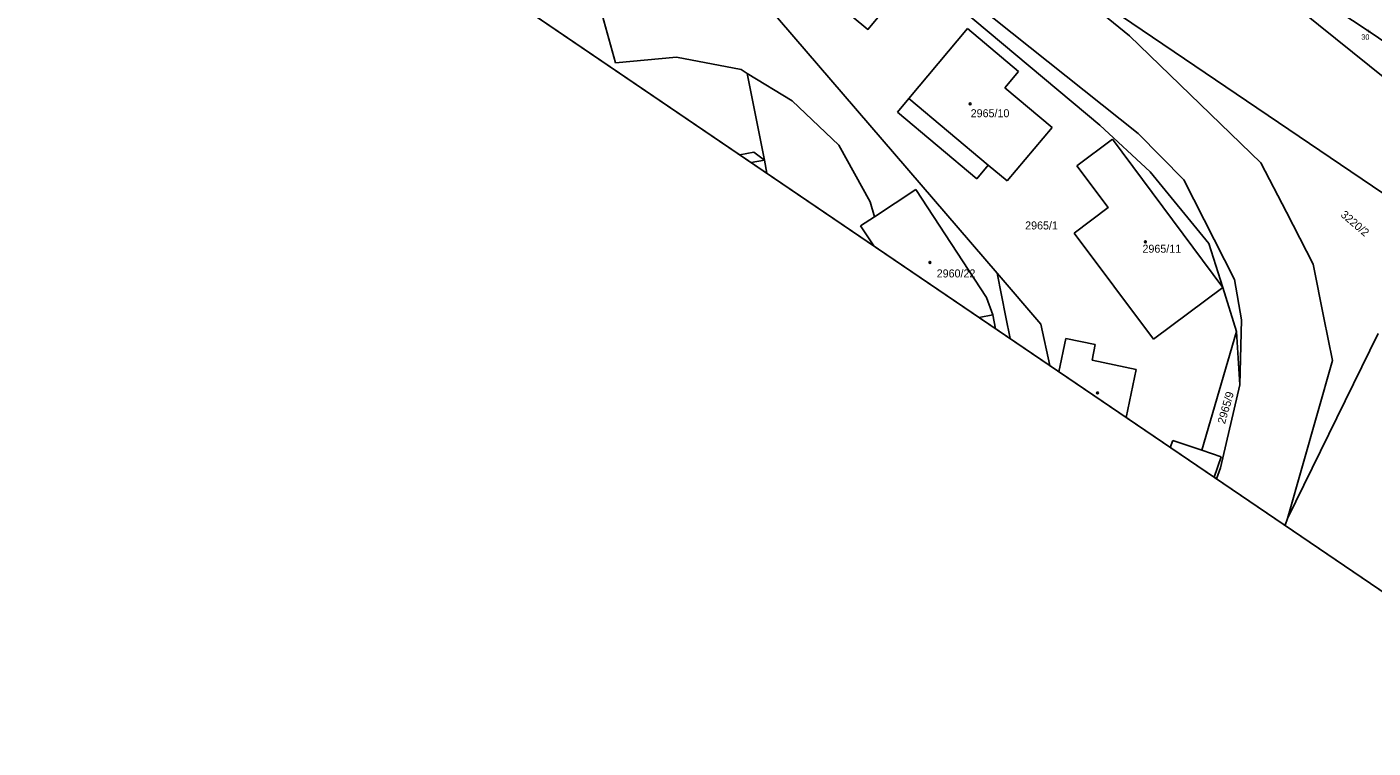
# Model space of a CAD drawing. Extents: x -621058 to -620110, y -1122807 to -1122030.
# Drawn here: x -620573.6 to -620321.3, y -1122806.7 to -1122671.6 of the extents above; entities that cross this region are included whole.
import ezdxf

# ---------------------------------------------------------------- set-up
doc = ezdxf.new("R2010")
doc.units = 0
for name, color, linetype in [('060601_EOV', 7, 'Continuous'), ('BODY', 7, 'Continuous'), ('BODY POPIS', 7, 'Continuous'), ('RÁMY', 7, 'Continuous'), ('Vrstva 53', 7, 'Continuous'), ('Vrstva 55', 7, 'Continuous'), ('Vrstva 56', 7, 'Continuous'), ('Vrstva 57', 7, 'Continuous')]:
    doc.layers.add(name, color=color, linetype=linetype)

msp = doc.modelspace()

# ---------------------------------------------------------------- linework, layer by layer
at = {"layer": '060601_EOV'}
msp.add_lwpolyline([(-620235.16, -1122712.24), (-620240.17, -1122718.34), (-620243.03, -1122716), (-620248.32, -1122722.77), (-620259.89, -1122713.57), (-620277.71, -1122700.9), (-620282.35, -1122705.3), (-620297.82, -1122689.49), (-620304.22, -1122684.86), (-620310.82, -1122680.06), (-620322.23, -1122672.32), (-620343.18, -1122658.46), (-620368.5, -1122642.9), (-620411.56, -1122614.92), (-620424.16, -1122607.09), (-620443.53, -1122595), (-620456.11, -1122587.12), (-620447.82, -1122572.96), (-620450.95, -1122571.45), (-620470.59, -1122561.48), (-620499.61, -1122545.57), (-620522.04, -1122531.47), (-620538.89, -1122521.21), (-620599.21, -1122483.22)], dxfattribs=at)
at = {"layer": 'RÁMY'}
for points in [[(-620974.7, -1122152.91), (-620192.94, -1122683.83), (-620276.37, -1122806.68), (-621058.13, -1122275.76)], [(-620887.83, -1122211.9), (-620192.94, -1122683.83), (-620276.37, -1122806.68), (-620971.26, -1122334.75)]]:
    msp.add_lwpolyline(points, close=True, dxfattribs=at)
at = {"layer": 'Vrstva 53'}
msp.add_line((-620309.9, -1122688.62), (-620334.71, -1122668.63), dxfattribs=at)
at = {"layer": 'Vrstva 55'}
for p, q in [((-620463.28, -1122678.3), (-620478.32, -1122624.38)), ((-620420.38, -1122629.64), (-620366.98, -1122673.23)), ((-620391.77, -1122717.74), (-620434.88, -1122667.63)), ((-620365.35, -1122691.52), (-620395.68, -1122667.41)), ((-620309.9, -1122688.62), (-620334.71, -1122668.63)), ((-620368.46, -1122669.58), (-620310.57, -1122708.76)), ((-620397.34, -1122671.88), (-620408.32, -1122685)), ((-620387.77, -1122679.92), (-620397.34, -1122671.88)), ((-620366.98, -1122673.23), (-620342.37, -1122697.07)), ((-620451.85, -1122677.25), (-620463.28, -1122678.3)), ((-620439.78, -1122679.56), (-620451.85, -1122677.25)), ((-620438.61, -1122680.28), (-620439.78, -1122679.56)), ((-620435.41, -1122696.52), (-620438.61, -1122680.28)), ((-620430.21, -1122685.42), (-620438.61, -1122680.28)), ((-620390.32, -1122682.97), (-620387.77, -1122679.92)), ((-620381.44, -1122690.4), (-620390.32, -1122682.97)), ((-620421.46, -1122693.76), (-620430.21, -1122685.42)), ((-620408.32, -1122685), (-620410.45, -1122687.55)), ((-620410.45, -1122687.55), (-620395.56, -1122700.01)), ((-620389.88, -1122700.43), (-620381.44, -1122690.4)), ((-620356.78, -1122700.2), (-620365.35, -1122691.52)), ((-620415.57, -1122704.35), (-620421.46, -1122693.76)), ((-620376.85, -1122697.59), (-620370.13, -1122692.59)), ((-620370.13, -1122692.59), (-620349.5, -1122720.4)), ((-620435.41, -1122696.52), (-620437.86, -1122697)), ((-620434.92, -1122699), (-620435.41, -1122696.52)), ((-620395.56, -1122700.01), (-620393.43, -1122697.46)), ((-620393.43, -1122697.46), (-620389.88, -1122700.43)), ((-620342.37, -1122697.07), (-620337.56, -1122706.31)), ((-620347.29, -1122718.92), (-620356.78, -1122700.2)), ((-620407.04, -1122702.06), (-620414.76, -1122707.13)), ((-620393.75, -1122722.26), (-620407.04, -1122702.06)), ((-620414.76, -1122707.13), (-620415.57, -1122704.35)), ((-620337.56, -1122706.31), (-620332.51, -1122716.01)), ((-620414.76, -1122707.13), (-620417.37, -1122708.84)), ((-620417.37, -1122708.84), (-620414.89, -1122712.61)), ((-620377.36, -1122710.19), (-620362.45, -1122730.09)), ((-620332.51, -1122716.01), (-620330.51, -1122726.08)), ((-620391.77, -1122717.74), (-620383.57, -1122727.26)), ((-620390.13, -1122725.98), (-620391.77, -1122717.74)), ((-620345.94, -1122726.44), (-620347.29, -1122718.92)), ((-620349.5, -1122720.4), (-620362.45, -1122730.09)), ((-620349.5, -1122720.4), (-620346.9, -1122728.66)), ((-620392.56, -1122725.51), (-620393.75, -1122722.26)), ((-620395.15, -1122726.01), (-620392.56, -1122725.51)), ((-620392.56, -1122725.51), (-620392.06, -1122728.11)), ((-620389.35, -1122729.95), (-620390.13, -1122725.98)), ((-620346.26, -1122738.61), (-620345.94, -1122726.44)), ((-620330.51, -1122726.08), (-620328.93, -1122734.05)), ((-620381.9, -1122735.01), (-620383.57, -1122727.26)), ((-620346.9, -1122728.66), (-620353.41, -1122750.9)), ((-620346.26, -1122738.61), (-620346.9, -1122728.66)), ((-620337.36, -1122763.66), (-620320.37, -1122729)), ((-620378.87, -1122729.94), (-620380.18, -1122736.18)), ((-620378.87, -1122729.94), (-620373.38, -1122731.07)), ((-620373.38, -1122731.07), (-620373.97, -1122734.01)), ((-620373.97, -1122734.01), (-620365.7, -1122735.74)), ((-620328.93, -1122734.05), (-620337.36, -1122763.66)), ((-620365.7, -1122735.74), (-620367.58, -1122744.74)), ((-620349.91, -1122754.18), (-620346.26, -1122738.61)), ((-620358.86, -1122749.03), (-620359.31, -1122750.35)), ((-620358.86, -1122749.03), (-620353.41, -1122750.9)), ((-620353.41, -1122750.9), (-620349.8, -1122752.13)), ((-620351.12, -1122755.91), (-620349.8, -1122752.13)), ((-620350.63, -1122756.24), (-620349.91, -1122754.18)), ((-620337.36, -1122763.66), (-620337.81, -1122764.95))]:
    msp.add_line(p, q, dxfattribs=at)
for points in [[(-620432.38, -1122643.03), (-620419.73, -1122650.41), (-620372.55, -1122689.97), (-620363.06, -1122698.75), (-620352.08, -1122712.18), (-620349.5, -1122720.4)], [(-620434.7, -1122656.53), (-620427.07, -1122647.39), (-620408.37, -1122662.86), (-620416.01, -1122672.06), (-620434.7, -1122656.53)], [(-620377.36, -1122710.19), (-620370.99, -1122705.44), (-620376.85, -1122697.59)]]:
    msp.add_lwpolyline(points, dxfattribs=at)
at = {"layer": 'Vrstva 56'}
for p, q in [((-620393.43, -1122697.46), (-620408.32, -1122685)), ((-620437.36, -1122695.04), (-620439.99, -1122695.56)), ((-620437.36, -1122695.04), (-620435.41, -1122696.52))]:
    msp.add_line(p, q, dxfattribs=at)
at = {"layer": 'Vrstva 57'}
for centre in [(-620396.83, -1122685.99), (-620363.99, -1122711.85), (-620404.37, -1122715.7), (-620372.96, -1122740.15)]:
    msp.add_circle(centre, 0.175, dxfattribs=at)

# ---------------------------------------------------------------- texts
at = {"layer": 'BODY'}
msp.add_text('+', height=1, dxfattribs=at).set_placement((-620322.56, -1122672.82))
at = {"layer": 'BODY POPIS'}
msp.add_text('30', height=1, dxfattribs=at).set_placement((-620323.52, -1122673.98))
at = {"layer": 'Vrstva 57'}
for s, p in [('2965/10', (-620396.73, -1122688.5)), ('2965/1', (-620386.52, -1122709.52)), ('2965/11', (-620364.53, -1122713.88)), ('2960/22', (-620403.1, -1122718.51))]:
    msp.add_text(s, height=1.5, dxfattribs=at).set_placement(p)
for s, rotation, p in [('3220/2', 319.5, (-620327.51, -1122706.97)), ('2965/9', 73.8221, (-620349.08, -1122746.06))]:
    msp.add_text(s, height=1.5, rotation=rotation, dxfattribs=at).set_placement(p)

doc.saveas('drawing.dxf')
